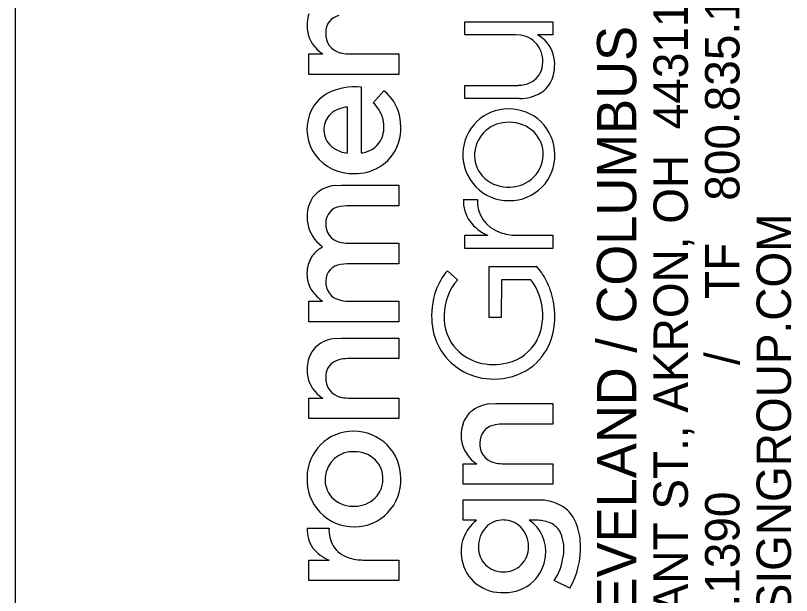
# Model space of a CAD drawing. Extents: x -4.4 to 34, y 0 to 22.
# Drawn here: x 32 to 33.125, y 3.094 to 3.936 of the extents above; entities that cross this region are included whole.
import ezdxf

# ---------------------------------------------------------------- set-up
doc = ezdxf.new("R2010")
doc.units = 0
doc.layers.add('PF_X_Ground_Line', color=7, linetype='Continuous')
doc.layers.add('UT_X_FO', color=7, linetype='Continuous')

msp = doc.modelspace()

# ---------------------------------------------------------------- linework, layer by layer
at = {"layer": 'PF_X_Ground_Line'}
for p, q in [((32.6515, 3.908), (32.6515, 3.9267)), ((32.6515, 3.9267), (32.7791, 3.9266)), ((32.7791, 3.9266), (32.7791, 3.908)), ((32.7249, 3.908), (32.6515, 3.908)), ((32.7328, 3.9073), (32.7249, 3.908)), ((32.7791, 3.908), (32.7569, 3.908)), ((32.4254, 3.8503), (32.4254, 3.8802)), ((32.4254, 3.8802), (32.4455, 3.8802)), ((32.4822, 3.8802), (32.5557, 3.8802)), ((32.5557, 3.8802), (32.5557, 3.8504)), ((32.5557, 3.8504), (32.4254, 3.8503)), ((32.5011, 3.8321), (32.5012, 3.7366)), ((32.5188, 3.8093), (32.5342, 3.8266)), ((32.6515, 3.8344), (32.7291, 3.8345)), ((32.6517, 3.8154), (32.6515, 3.8344)), ((32.7307, 3.8154), (32.6517, 3.8154)), ((32.4814, 3.7364), (32.4814, 3.803)), ((32.4802, 3.7363), (32.4814, 3.7364)), ((32.4633, 3.6891), (32.4726, 3.6897)), ((32.4726, 3.6897), (32.5556, 3.6897)), ((32.5556, 3.6897), (32.5557, 3.6598)), ((32.6493, 3.6691), (32.6698, 3.6691)), ((32.4806, 3.6598), (32.471, 3.6588)), ((32.5557, 3.6598), (32.4806, 3.6598)), ((32.6515, 3.598), (32.6515, 3.617)), ((32.6515, 3.617), (32.6848, 3.617)), ((32.726, 3.617), (32.7791, 3.617)), ((32.7791, 3.617), (32.779, 3.598)), ((32.4444, 3.5992), (32.4446, 3.6007)), ((32.4822, 3.6055), (32.5557, 3.6055)), ((32.5557, 3.6055), (32.5557, 3.5757)), ((32.779, 3.598), (32.6515, 3.598)), ((32.4809, 3.5757), (32.4714, 3.5747)), ((32.5557, 3.5757), (32.4809, 3.5757)), ((32.6868, 3.5718), (32.7552, 3.5719)), ((32.6868, 3.4978), (32.6868, 3.5718)), ((32.6264, 3.5655), (32.6411, 3.5524)), ((32.7045, 3.5524), (32.7043, 3.4978)), ((32.7474, 3.5523), (32.7045, 3.5524)), ((32.4254, 3.4915), (32.4254, 3.5214)), ((32.4254, 3.5214), (32.4451, 3.5214)), ((32.4821, 3.5214), (32.5557, 3.5214)), ((32.5557, 3.5214), (32.5557, 3.4916)), ((32.75, 3.5), (32.75, 3.5)), ((32.5557, 3.4916), (32.4254, 3.4915)), ((32.7043, 3.4978), (32.6868, 3.4978)), ((32.4644, 3.4674), (32.4729, 3.4678)), ((32.4729, 3.4678), (32.5557, 3.4678)), ((32.5557, 3.4678), (32.5557, 3.438)), ((32.5557, 3.438), (32.4814, 3.438)), ((32.4254, 3.3509), (32.4254, 3.3807)), ((32.4254, 3.3807), (32.4455, 3.3807)), ((32.4822, 3.3807), (32.5557, 3.3807)), ((32.5557, 3.3807), (32.5557, 3.351)), ((32.6878, 3.3722), (32.6963, 3.3727)), ((32.6963, 3.3727), (32.7792, 3.3727)), ((32.7792, 3.3727), (32.7792, 3.3429)), ((32.5557, 3.351), (32.4254, 3.3509)), ((32.7792, 3.3429), (32.7048, 3.3428)), ((32.6489, 3.2557), (32.6489, 3.2855)), ((32.6489, 3.2855), (32.669, 3.2855)), ((32.7057, 3.2855), (32.7791, 3.2855)), ((32.7791, 3.2855), (32.7792, 3.2558)), ((32.7792, 3.2558), (32.6489, 3.2557)), ((32.6489, 3.2034), (32.6489, 3.2332)), ((32.6489, 3.2332), (32.7524, 3.2332)), ((32.7524, 3.2332), (32.7619, 3.2329)), ((32.6684, 3.2034), (32.6489, 3.2034)), ((32.7576, 3.2036), (32.7449, 3.2036)), ((32.423, 3.1919), (32.4545, 3.1919)), ((32.4254, 3.1159), (32.4254, 3.1458)), ((32.4254, 3.1458), (32.4547, 3.1458)), ((32.5041, 3.1458), (32.5557, 3.1457)), ((32.5557, 3.1457), (32.5556, 3.1159)), ((32.5556, 3.1159), (32.4254, 3.1159)), ((32.8036, 3.1049), (32.7812, 3.116))]:
    msp.add_line(p, q, dxfattribs=at)
for points in [[(32.7328, 3.9073), (32.7249, 3.908), (32.6515, 3.908), (32.6515, 3.9267), (32.7791, 3.9266), (32.7791, 3.908), (32.7569, 3.908)], [(32.4254, 3.8503), (32.4254, 3.8802), (32.4455, 3.8802)], [(32.4822, 3.8802), (32.5557, 3.8802), (32.5557, 3.8504), (32.4254, 3.8503)], [(32.5011, 3.8321), (32.5012, 3.7366)], [(32.5188, 3.8093), (32.5342, 3.8266)], [(32.7307, 3.8154), (32.6517, 3.8154), (32.6515, 3.8344), (32.7291, 3.8345)], [(32.4802, 3.7363), (32.4814, 3.7364), (32.4814, 3.803)], [(32.4633, 3.6891), (32.4726, 3.6897), (32.5556, 3.6897), (32.5557, 3.6598), (32.4806, 3.6598), (32.471, 3.6588)], [(32.6493, 3.6691), (32.6698, 3.6691)], [(32.6515, 3.598), (32.6515, 3.617), (32.6848, 3.617)], [(32.726, 3.617), (32.7791, 3.617), (32.779, 3.598), (32.6515, 3.598)], [(32.4444, 3.5992), (32.4446, 3.6007)], [(32.4822, 3.6055), (32.5557, 3.6055), (32.5557, 3.5757), (32.4809, 3.5757), (32.4714, 3.5747)], [(32.7474, 3.5523), (32.7045, 3.5524), (32.7043, 3.4978), (32.6868, 3.4978), (32.6868, 3.5718), (32.7552, 3.5719)], [(32.6264, 3.5655), (32.6411, 3.5524)], [(32.4254, 3.4915), (32.4254, 3.5214), (32.4451, 3.5214)], [(32.4821, 3.5214), (32.5557, 3.5214), (32.5557, 3.4916), (32.4254, 3.4915)], [(32.4644, 3.4674), (32.4729, 3.4678), (32.5557, 3.4678), (32.5557, 3.438), (32.4814, 3.438)], [(32.4254, 3.3509), (32.4254, 3.3807), (32.4455, 3.3807)], [(32.4822, 3.3807), (32.5557, 3.3807), (32.5557, 3.351), (32.4254, 3.3509)], [(32.6878, 3.3722), (32.6963, 3.3727), (32.7792, 3.3727), (32.7792, 3.3429), (32.7048, 3.3428)], [(32.6489, 3.2557), (32.6489, 3.2855), (32.669, 3.2855)], [(32.7057, 3.2855), (32.7791, 3.2855), (32.7792, 3.2558), (32.6489, 3.2557)], [(32.6684, 3.2034), (32.6489, 3.2034), (32.6489, 3.2332), (32.7524, 3.2332), (32.7619, 3.2329)], [(32.7576, 3.2036), (32.7449, 3.2036)], [(32.423, 3.1919), (32.4545, 3.1919)], [(32.4254, 3.1159), (32.4254, 3.1458), (32.4547, 3.1458)], [(32.5041, 3.1458), (32.5557, 3.1457), (32.5556, 3.1159), (32.4254, 3.1159)], [(32.8036, 3.1049), (32.7812, 3.116)]]:
    msp.add_lwpolyline(points, dxfattribs=at)
for centre, radius, start, end in [((32.4787, 3.9211), 0.056, 162.274, 187.7917), ((32.4787, 3.9211), 0.056, 162.274, 187.7917), ((32.4748, 3.9116), 0.025, 103.6868, 182.214), ((32.4748, 3.9116), 0.025, 103.6868, 182.214), ((32.4703, 3.9209), 0.0476, 188.9646, 238.6987), ((32.4703, 3.9209), 0.0476, 188.9646, 238.6987), ((32.4774, 3.9085), 0.0276, 175.5844, 255.1382), ((32.4774, 3.9085), 0.0276, 175.5844, 255.1382), ((32.7271, 3.87), 0.0377, 33.5008, 81.3295), ((32.7271, 3.87), 0.0377, 33.5008, 81.3295), ((32.7324, 3.8648), 0.0496, 17.6221, 60.3897), ((32.7324, 3.8648), 0.0496, 17.6221, 60.3897), ((32.4818, 3.9224), 0.0421, 254.0891, 270.5284), ((32.4818, 3.9224), 0.0421, 254.0891, 270.5284), ((32.7241, 3.8695), 0.0405, 346.5618, 31.7539), ((32.7241, 3.8695), 0.0405, 346.5618, 31.7539), ((32.7234, 3.8641), 0.0584, 339.162, 15.6148), ((32.7234, 3.8641), 0.0584, 339.162, 15.6148), ((32.7337, 3.8662), 0.0304, 294.6321, 348.4863), ((32.7337, 3.8662), 0.0304, 294.6321, 348.4863), ((32.7275, 3.8808), 0.0463, 271.952, 294.0894), ((32.7275, 3.8808), 0.0463, 271.952, 294.0894), ((32.739, 3.859), 0.042, 303.1039, 338.1561), ((32.739, 3.859), 0.042, 303.1039, 338.1561), ((32.4918, 3.7487), 0.0839, 83.6212, 118.2845), ((32.4918, 3.7487), 0.0839, 83.6212, 118.2845), ((32.494, 3.7763), 0.0644, 13.5328, 51.3627), ((32.494, 3.7763), 0.0644, 13.5328, 51.3627), ((32.4789, 3.7737), 0.0558, 118.8294, 160.6224), ((32.4789, 3.7737), 0.0558, 118.8294, 160.6224), ((32.7321, 3.8726), 0.0571, 268.627, 301.4778), ((32.7321, 3.8726), 0.0571, 268.627, 301.4778), ((32.4844, 3.7607), 0.0424, 94.0131, 130.8806), ((32.4844, 3.7607), 0.0424, 94.0131, 130.8806), ((32.4803, 3.7702), 0.0549, 19.0387, 45.4432), ((32.4803, 3.7702), 0.0549, 19.0387, 45.4432), ((32.487, 3.7707), 0.0644, 160.5214, 215.7815), ((32.487, 3.7707), 0.0644, 160.5214, 215.7815), ((32.477, 3.7709), 0.0298, 132.9855, 177.1802), ((32.477, 3.7709), 0.0298, 132.9855, 177.1802), ((32.7143, 3.7348), 0.0655, 89.4821, 178.7775), ((32.7143, 3.7348), 0.0655, 89.4821, 178.7775), ((32.7158, 3.7341), 0.0662, 0.4227, 90.7613), ((32.7158, 3.7341), 0.0662, 0.4227, 90.7613), ((32.4872, 3.7743), 0.047, 344.6072, 17.0067), ((32.4872, 3.7743), 0.047, 344.6072, 17.0067), ((32.4829, 3.7738), 0.0758, 339.3543, 13.3771), ((32.4829, 3.7738), 0.0758, 339.3543, 13.3771), ((32.714, 3.7324), 0.0485, 87.6883, 175.017), ((32.714, 3.7324), 0.0485, 87.6883, 175.017), ((32.7166, 3.7304), 0.0505, 44.912, 90.7591), ((32.7166, 3.7304), 0.0505, 44.912, 90.7591), ((32.4782, 3.7697), 0.0311, 175.0014, 223.2876), ((32.4782, 3.7697), 0.0311, 175.0014, 223.2876), ((32.499, 3.7718), 0.035, 288.0108, 343.5536), ((32.499, 3.7718), 0.035, 288.0108, 343.5536), ((32.7196, 3.7345), 0.0455, 358.3228, 43.8349), ((32.7196, 3.7345), 0.0455, 358.3228, 43.8349), ((32.4855, 3.7783), 0.0423, 225.0645, 262.797), ((32.4855, 3.7783), 0.0423, 225.0645, 262.797), ((32.4955, 3.7698), 0.0626, 300.9439, 338.7322), ((32.4955, 3.7698), 0.0626, 300.9439, 338.7322), ((32.5013, 3.7568), 0.0202, 269.7004, 294.8729), ((32.5013, 3.7568), 0.0202, 269.7004, 294.8729), ((32.7148, 3.7334), 0.0661, 177.5373, 270.9452), ((32.7148, 3.7334), 0.0661, 177.5373, 270.9452), ((32.7108, 3.7331), 0.0453, 175.5147, 221.4205), ((32.7108, 3.7331), 0.0453, 175.5147, 221.4205), ((32.4891, 3.7752), 0.0687, 217.7434, 271.6561), ((32.4891, 3.7752), 0.0687, 217.7434, 271.6561), ((32.7167, 3.7327), 0.0654, 269.3083, 1.6791), ((32.7167, 3.7327), 0.0654, 269.3083, 1.6791), ((32.7193, 3.7337), 0.0457, 308.9038, 359.3095), ((32.7193, 3.7337), 0.0457, 308.9038, 359.3095), ((32.492, 3.777), 0.0706, 269.2053, 300.3357), ((32.492, 3.777), 0.0706, 269.2053, 300.3357), ((32.714, 3.7373), 0.0505, 222.6626, 268.3733), ((32.714, 3.7373), 0.0505, 222.6626, 268.3733), ((32.7157, 3.7386), 0.0518, 266.5531, 308.6725), ((32.7157, 3.7386), 0.0518, 266.5531, 308.6725), ((32.4664, 3.644), 0.0452, 93.9112, 142.3072), ((32.4664, 3.644), 0.0452, 93.9112, 142.3072), ((32.4759, 3.6437), 0.0532, 148.2879, 233.9556), ((32.4759, 3.6437), 0.0532, 148.2879, 233.9556), ((32.6988, 3.6666), 0.0495, 177.1621, 216.2802), ((32.6988, 3.6666), 0.0495, 177.1621, 216.2802), ((32.7173, 3.6664), 0.0476, 176.7699, 252.1504), ((32.7173, 3.6664), 0.0476, 176.7699, 252.1504), ((32.4738, 3.635), 0.024, 96.7576, 181.6251), ((32.4738, 3.635), 0.024, 96.7576, 181.6251), ((32.4758, 3.6324), 0.026, 175.8157, 256.1672), ((32.4758, 3.6324), 0.026, 175.8157, 256.1672), ((32.7098, 3.6755), 0.0637, 216.9153, 246.8862), ((32.7098, 3.6755), 0.0637, 216.9153, 246.8862), ((32.7269, 3.6917), 0.0747, 251.1388, 269.3469), ((32.7269, 3.6917), 0.0747, 251.1388, 269.3469), ((32.4817, 3.6505), 0.045, 254.3463, 270.6103), ((32.4817, 3.6505), 0.045, 254.3463, 270.6103), ((32.4619, 3.5645), 0.0387, 139.5245, 154.847), ((32.4619, 3.5645), 0.0387, 139.5245, 154.847), ((32.4638, 3.5627), 0.0414, 117.9163, 139.243), ((32.4638, 3.5627), 0.0414, 117.9163, 139.243), ((32.4714, 3.5612), 0.0488, 156.0638, 187.3493), ((32.4714, 3.5612), 0.0488, 156.0638, 187.3493), ((32.4742, 3.5506), 0.0243, 96.5532, 179.949), ((32.4742, 3.5506), 0.0243, 96.5532, 179.949), ((32.725, 3.5394), 0.0444, 30.9891, 47.161), ((32.725, 3.5394), 0.0444, 30.9891, 47.161), ((32.7016, 3.5019), 0.0986, 139.7948, 159.137), ((32.7016, 3.5019), 0.0986, 139.7948, 159.137), ((32.6709, 3.5002), 0.1111, 25.3031, 33.9618), ((32.6709, 3.5002), 0.1111, 25.3031, 33.9618), ((32.4646, 3.5597), 0.0418, 186.5579, 213.3885), ((32.4646, 3.5597), 0.0418, 186.5579, 213.3885), ((32.4761, 3.5486), 0.0263, 175.722, 255.7863), ((32.4761, 3.5486), 0.0263, 175.722, 255.7863), ((32.699, 3.5008), 0.0775, 138.258, 179.7006), ((32.699, 3.5008), 0.0775, 138.258, 179.7006), ((32.6789, 3.501), 0.0856, 10.0751, 36.8319), ((32.6789, 3.501), 0.0856, 10.0751, 36.8319), ((32.6704, 3.4999), 0.1117, 8.8034, 25.3348), ((32.6704, 3.4999), 0.1117, 8.8034, 25.3348), ((32.4789, 3.5708), 0.0598, 214.7043, 235.6872), ((32.4789, 3.5708), 0.0598, 214.7043, 235.6872), ((32.7187, 3.4997), 0.1154, 161.1438, 185.6281), ((32.7187, 3.4997), 0.1154, 161.1438, 185.6281), ((32.4819, 3.5652), 0.0438, 253.6672, 270.1498), ((32.4819, 3.5652), 0.0438, 253.6672, 270.1498), ((32.6842, 3.5006), 0.0804, 333.4669, 11.0367), ((32.6842, 3.5006), 0.0804, 333.4669, 11.0367), ((32.6756, 3.4998), 0.1065, 338.2887, 9.2855), ((32.6756, 3.4998), 0.1065, 338.2887, 9.2855), ((32.6881, 3.4973), 0.0668, 176.6658, 223.6912), ((32.6881, 3.4973), 0.0668, 176.6658, 223.6912), ((32.6934, 3.497), 0.0899, 185.5077, 212.0129), ((32.6934, 3.497), 0.0899, 185.5077, 212.0129), ((32.4687, 3.4177), 0.0499, 94.9706, 130.2248), ((32.4687, 3.4177), 0.0499, 94.9706, 130.2248), ((32.4635, 3.426), 0.0402, 132.2238, 161.6823), ((32.4635, 3.426), 0.0402, 132.2238, 161.6823), ((32.6987, 3.4955), 0.0652, 282.8815, 331.8147), ((32.6987, 3.4955), 0.0652, 282.8815, 331.8147), ((32.6984, 3.4917), 0.0824, 305.0306, 337.6757), ((32.6984, 3.4917), 0.0824, 305.0306, 337.6757), ((32.6921, 3.4975), 0.0891, 212.7022, 270.714), ((32.6921, 3.4975), 0.0891, 212.7022, 270.714), ((32.6905, 3.5001), 0.0704, 224.0215, 253.88), ((32.6905, 3.5001), 0.0704, 224.0215, 253.88), ((32.4787, 3.4216), 0.056, 162.274, 187.7917), ((32.4787, 3.4216), 0.056, 162.274, 187.7917), ((32.4748, 3.4121), 0.025, 103.6868, 182.214), ((32.4748, 3.4121), 0.025, 103.6868, 182.214), ((32.4811, 3.392), 0.046, 89.6051, 105.3303), ((32.4811, 3.392), 0.046, 89.6051, 105.3303), ((32.6932, 3.5125), 0.0831, 254.4535, 283.9512), ((32.6932, 3.5125), 0.0831, 254.4535, 283.9512), ((32.6943, 3.4998), 0.0914, 269.3273, 304.1963), ((32.6943, 3.4998), 0.0914, 269.3273, 304.1963), ((32.4703, 3.4214), 0.0476, 188.9646, 238.6987), ((32.4703, 3.4214), 0.0476, 188.9646, 238.6987), ((32.4774, 3.409), 0.0276, 175.5844, 255.1382), ((32.4774, 3.409), 0.0276, 175.5844, 255.1382), ((32.4818, 3.4229), 0.0421, 254.0891, 270.5284), ((32.4818, 3.4229), 0.0421, 254.0891, 270.5284), ((32.6922, 3.3225), 0.0499, 94.9706, 130.2248), ((32.6922, 3.3225), 0.0499, 94.9706, 130.2248), ((32.6869, 3.3309), 0.0402, 132.2238, 161.6823), ((32.6869, 3.3309), 0.0402, 132.2238, 161.6823), ((32.7022, 3.3264), 0.056, 162.274, 187.7917), ((32.7022, 3.3264), 0.056, 162.274, 187.7917), ((32.7045, 3.2968), 0.046, 89.6051, 105.3303), ((32.7045, 3.2968), 0.046, 89.6051, 105.3303), ((32.4901, 3.2654), 0.0674, 89.8476, 179.6405), ((32.4901, 3.2654), 0.0674, 89.8476, 179.6405), ((32.4906, 3.2647), 0.0681, 359.5401, 90.2114), ((32.4906, 3.2647), 0.0681, 359.5401, 90.2114), ((32.6983, 3.3169), 0.025, 103.6868, 182.214), ((32.6983, 3.3169), 0.025, 103.6868, 182.214), ((32.6937, 3.3262), 0.0476, 188.9646, 238.6987), ((32.6937, 3.3262), 0.0476, 188.9646, 238.6987), ((32.7008, 3.3138), 0.0276, 175.5844, 255.1382), ((32.7008, 3.3138), 0.0276, 175.5844, 255.1382), ((32.4892, 3.2626), 0.0404, 87.0481, 175.5726), ((32.4892, 3.2626), 0.0404, 87.0481, 175.5726), ((32.492, 3.26), 0.043, 45.8426, 90.9801), ((32.492, 3.26), 0.043, 45.8426, 90.9801), ((32.4946, 3.2642), 0.0382, 357.8857, 44.159), ((32.4946, 3.2642), 0.0382, 357.8857, 44.159), ((32.7053, 3.3277), 0.0421, 254.0891, 270.5284), ((32.7053, 3.3277), 0.0421, 254.0891, 270.5284), ((32.4908, 3.2621), 0.0682, 176.8344, 270.4038), ((32.4908, 3.2621), 0.0682, 176.8344, 270.4038), ((32.4873, 3.2625), 0.0385, 175.1538, 221.1471), ((32.4873, 3.2625), 0.0385, 175.1538, 221.1471), ((32.4912, 3.2614), 0.0675, 270.0624, 2.3776), ((32.4912, 3.2614), 0.0675, 270.0624, 2.3776), ((32.4945, 3.2632), 0.0383, 308.2894, 359.4347), ((32.4945, 3.2632), 0.0383, 308.2894, 359.4347), ((32.4892, 3.2661), 0.0423, 223.0999, 268.8089), ((32.4892, 3.2661), 0.0423, 223.0999, 268.8089), ((32.491, 3.2679), 0.0442, 266.5651, 308.0608), ((32.491, 3.2679), 0.0442, 266.5651, 308.0608), ((32.7591, 3.1679), 0.065, 53.4034, 87.4906), ((32.7591, 3.1679), 0.065, 53.4034, 87.4906), ((32.7652, 3.1804), 0.0514, 21.6075, 50.5577), ((32.7652, 3.1804), 0.0514, 21.6075, 50.5577), ((32.7029, 3.1581), 0.0569, 127.3748, 192.2247), ((32.7029, 3.1581), 0.0569, 127.3748, 192.2247), ((32.7069, 3.1693), 0.0346, 88.473, 136.4256), ((32.7069, 3.1693), 0.0346, 88.473, 136.4256), ((32.7081, 3.1696), 0.0342, 44.2719, 90.4762), ((32.7081, 3.1696), 0.0342, 44.2719, 90.4762), ((32.7142, 3.1583), 0.0547, 352.1125, 55.923), ((32.7142, 3.1583), 0.0547, 352.1125, 55.923), ((32.7567, 3.1572), 0.0463, 65.0169, 88.8011), ((32.7567, 3.1572), 0.0463, 65.0169, 88.8011), ((32.7626, 3.1716), 0.0309, 26.2681, 63.803), ((32.7626, 3.1716), 0.0309, 26.2681, 63.803), ((32.7307, 3.1671), 0.0884, 1.1514, 21.3627), ((32.7307, 3.1671), 0.0884, 1.1514, 21.3627), ((32.4662, 3.1888), 0.0433, 175.8731, 216.3475), ((32.4662, 3.1888), 0.0433, 175.8731, 216.3475), ((32.5009, 3.1895), 0.0464, 176.9688, 209.6064), ((32.5009, 3.1895), 0.0464, 176.9688, 209.6064), ((32.7114, 3.166), 0.0401, 137.4674, 182.3324), ((32.7114, 3.166), 0.0401, 137.4674, 182.3324), ((32.7037, 3.166), 0.04, 358.5714, 43.5376), ((32.7037, 3.166), 0.04, 358.5714, 43.5376), ((32.7357, 3.1615), 0.0595, 349.3073, 23.4307), ((32.7357, 3.1615), 0.0595, 349.3073, 23.4307), ((32.4747, 3.1972), 0.0551, 218.0981, 248.7907), ((32.4747, 3.1972), 0.0551, 218.0981, 248.7907), ((32.4951, 3.1881), 0.0408, 211.9447, 253.2028), ((32.4951, 3.1881), 0.0408, 211.9447, 253.2028), ((32.7065, 3.1637), 0.0351, 178.8821, 271.0837), ((32.7065, 3.1637), 0.0351, 178.8821, 271.0837), ((32.7082, 3.164), 0.0355, 268.2788, 1.5502), ((32.7082, 3.164), 0.0355, 268.2788, 1.5502), ((32.7054, 3.1624), 0.1138, 329.6388, 3.26), ((32.7054, 3.1624), 0.1138, 329.6388, 3.26), ((32.7099, 3.1571), 0.0589, 313.742, 353.8554), ((32.7099, 3.1571), 0.0589, 313.742, 353.8554), ((32.7074, 3.1633), 0.0877, 327.3149, 351.5748), ((32.7074, 3.1633), 0.0877, 327.3149, 351.5748), ((32.5047, 3.2165), 0.0707, 252.4655, 269.573), ((32.5047, 3.2165), 0.0707, 252.4655, 269.573), ((32.7046, 3.157), 0.0584, 190.7518, 231.2892), ((32.7046, 3.157), 0.0584, 190.7518, 231.2892), ((32.7063, 3.1611), 0.0627, 232.4606, 272.5902), ((32.7063, 3.1611), 0.0627, 232.4606, 272.5902), ((32.7095, 3.159), 0.0605, 269.6361, 312.7088), ((32.7095, 3.159), 0.0605, 269.6361, 312.7088)]:
    msp.add_arc(centre, radius, start, end, dxfattribs=at)
at = {"layer": 'UT_X_FO'}
msp.add_line((32, 0.5), (32, 21.5), dxfattribs=at)

# ---------------------------------------------------------------- texts
at = {"layer": 'PF_X_Ground_Line'}
for s, height, p in [('800.835.1390', 0.049846, (33.0497, 3.6671)), ('450 GRANT ST., AKRON, OH  44311', 0.049846, (32.9749, 2.8374)), ('AKRON / CLEVELAND / COLUMBUS', 0.056969, (32.9001, 2.638)), ('ENVDESIGNGROUP.COM', 0.049846, (33.1244, 2.8374)), ('TF', 0.04985, (33.0497, 3.5246)), ('/  ', 0.04985, (33.0497, 3.4288)), ('330.375.1390', 0.049846, (33.0497, 2.8374))]:
    msp.add_text(s, height=height, rotation=90, dxfattribs=at).set_placement(p)

doc.saveas('drawing.dxf')
